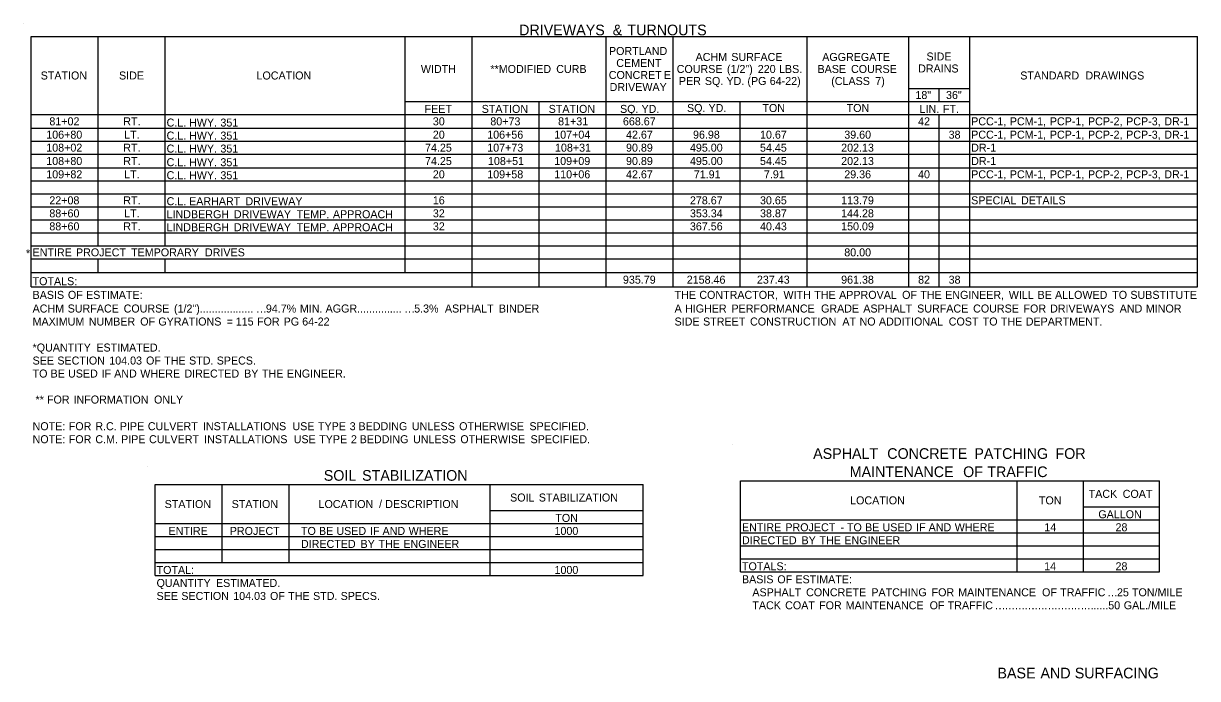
# Model space of a CAD drawing. Extents: x 1197542 to 1207068, y 230488 to 237324.
# Drawn here: x 1201721 to 1202601, y 232270 to 232761 of the extents above; entities that cross this region are included whole.
import ezdxf

# ---------------------------------------------------------------- set-up
doc = ezdxf.new("R2010")
doc.units = 0
doc.layers.add('Default', color=7, linetype='Continuous')

msp = doc.modelspace()

# ---------------------------------------------------------------- linework, layer by layer
at = {"layer": 'Default'}
for p, q in [((1201721.23, 232761.28), (1201721.23, 232761.28)), ((1201727.08, 232751.53), (1202601.17, 232751.53)), ((1201727.08, 232563.84), (1201727.08, 232751.53)), ((1201727.08, 232563.84), (1201727.08, 232751.53)), ((1201777.29, 232594.56), (1201777.29, 232751.53)), ((1201827.5, 232594.56), (1201827.5, 232751.53)), ((1202007.39, 232574.57), (1202007.39, 232751.53)), ((1202057.6, 232563.84), (1202057.6, 232751.53)), ((1202158.03, 232563.84), (1202158.03, 232751.53)), ((1202208.24, 232563.84), (1202208.24, 232751.53)), ((1202308.67, 232563.84), (1202308.67, 232751.53)), ((1202384.72, 232563.84), (1202384.72, 232751.53)), ((1202430.54, 232574.57), (1202430.54, 232751.53)), ((1202430.54, 232563.84), (1202430.54, 232751.53)), ((1202601.17, 232563.84), (1202601.17, 232751.53)), ((1202601.17, 232563.84), (1202601.17, 232751.53)), ((1202384.72, 232712.53), (1202430.54, 232712.53)), ((1202407.63, 232702.78), (1202407.63, 232712.53)), ((1202407.63, 232702.78), (1202407.63, 232712.53)), ((1202007.39, 232702.78), (1202430.54, 232702.78)), ((1202057.6, 232693.03), (1202057.6, 232702.78)), ((1202107.82, 232563.84), (1202107.82, 232702.78)), ((1202208.24, 232693.03), (1202208.24, 232702.78)), ((1202258.45, 232563.84), (1202258.45, 232702.78)), ((1202308.67, 232563.84), (1202308.67, 232702.78)), ((1202384.72, 232702.78), (1202430.54, 232702.78)), ((1201727.08, 232693.03), (1202601.17, 232693.03)), ((1201777.29, 232594.56), (1201777.29, 232693.03)), ((1201827.5, 232594.56), (1201827.5, 232693.03)), ((1202007.39, 232594.56), (1202007.39, 232693.03)), ((1202107.82, 232563.84), (1202107.82, 232693.03)), ((1202158.03, 232563.84), (1202158.03, 232693.03)), ((1202407.63, 232574.57), (1202407.63, 232693.03)), ((1202407.63, 232563.84), (1202407.63, 232693.03)), ((1202430.54, 232693.03), (1202601.17, 232693.03)), ((1201727.08, 232682.79), (1202430.54, 232682.79)), ((1202430.54, 232682.79), (1202601.17, 232682.79)), ((1202430.54, 232682.79), (1202601.17, 232682.79)), ((1201727.08, 232673.04), (1202601.17, 232673.04)), ((1202430.54, 232673.04), (1202601.17, 232673.04)), ((1201727.08, 232663.29), (1202601.17, 232663.29)), ((1201727.08, 232653.06), (1202430.54, 232653.06)), ((1202430.54, 232653.06), (1202601.17, 232653.06)), ((1202430.54, 232653.06), (1202601.17, 232653.06)), ((1201727.08, 232643.31), (1202601.17, 232643.31)), ((1202430.54, 232643.31), (1202601.17, 232643.31)), ((1201727.08, 232633.56), (1202601.17, 232633.56)), ((1201727.08, 232623.81), (1202601.17, 232623.81)), ((1201727.08, 232614.06), (1202601.17, 232614.06)), ((1201727.08, 232604.31), (1202601.17, 232604.31)), ((1201727.08, 232594.56), (1202601.17, 232594.56)), ((1201777.29, 232594.56), (1201827.5, 232594.56)), ((1201827.5, 232594.56), (1202601.17, 232594.56)), ((1201727.08, 232584.81), (1202601.17, 232584.81)), ((1201777.29, 232574.57), (1201777.29, 232584.81)), ((1201777.29, 232574.57), (1201777.29, 232584.81)), ((1201827.5, 232574.57), (1201827.5, 232584.81)), ((1201827.5, 232574.57), (1201827.5, 232584.81)), ((1202007.39, 232574.57), (1202007.39, 232584.81)), ((1201727.08, 232574.57), (1202601.17, 232574.57)), ((1202057.6, 232563.84), (1202057.6, 232574.57)), ((1202208.24, 232574.57), (1202258.45, 232574.57)), ((1202258.45, 232574.57), (1202384.72, 232574.57)), ((1202384.72, 232574.57), (1202430.54, 232574.57)), ((1202430.54, 232574.57), (1202601.17, 232574.57)), ((1201727.08, 232563.84), (1202601.17, 232563.84)), ((1202252.9, 232445.67), (1202252.9, 232445.67)), ((1201814.15, 232429.27), (1201814.15, 232429.27)), ((1202258.75, 232418.37), (1202572.7, 232418.37)), ((1202258.75, 232350.12), (1202258.75, 232418.37)), ((1202258.75, 232350.12), (1202258.75, 232418.37)), ((1202465.94, 232350.12), (1202465.94, 232418.37)), ((1202515.66, 232350.12), (1202515.66, 232418.37)), ((1202572.7, 232350.12), (1202572.7, 232418.37)), ((1202572.7, 232398.87), (1202572.7, 232418.37)), ((1201820, 232415.62), (1202185.63, 232415.62)), ((1201820, 232347.37), (1201820, 232415.62)), ((1201820, 232347.37), (1201820, 232415.62)), ((1201870.21, 232357.12), (1201870.21, 232415.62)), ((1201920.43, 232357.12), (1201920.43, 232415.62)), ((1202071.06, 232347.37), (1202071.06, 232415.62)), ((1202185.63, 232347.37), (1202185.63, 232415.62)), ((1202185.63, 232347.37), (1202185.63, 232415.62)), ((1202071.06, 232396.12), (1202185.63, 232396.12)), ((1202515.66, 232398.87), (1202572.7, 232398.87)), ((1202515.66, 232350.12), (1202515.66, 232398.87)), ((1201820, 232386.37), (1202185.63, 232386.37)), ((1201820, 232386.37), (1202185.63, 232386.37)), ((1201870.21, 232357.12), (1201870.21, 232386.37)), ((1201920.43, 232357.12), (1201920.43, 232386.37)), ((1202071.06, 232357.12), (1202071.06, 232386.37)), ((1202258.75, 232389.12), (1202572.7, 232389.12)), ((1202465.94, 232350.12), (1202465.94, 232389.12)), ((1202572.7, 232369.62), (1202572.7, 232389.12)), ((1201820, 232376.62), (1202185.63, 232376.62)), ((1202258.75, 232379.37), (1202572.7, 232379.37)), ((1201820, 232366.87), (1202185.63, 232366.87)), ((1202258.75, 232369.62), (1202572.7, 232369.62)), ((1201820, 232357.12), (1201870.21, 232357.12)), ((1201820, 232357.12), (1202185.63, 232357.12)), ((1202258.75, 232359.87), (1202572.7, 232359.87)), ((1202572.7, 232350.12), (1202572.7, 232359.87)), ((1202258.75, 232350.12), (1202572.7, 232350.12)), ((1201820, 232347.37), (1202185.63, 232347.37))]:
    msp.add_line(p, q, dxfattribs=at)

# ---------------------------------------------------------------- texts
for s, height, p in [('DRIVEWAYS', 8, (1202092.72, 232752.41)), (' &', 8, (1202159.87, 232752.41)), (' TURNOUTS', 8, (1202170.87, 232752.41)), ('PORTLAND', 6, (1202160.05, 232737.66)), ('CEMENT', 6, (1202165.52, 232728.66)), ('ACHM', 6, (1202224.96, 232733.16)), (' SURFACE', 6, (1202249.51, 232733.16)), ('AGGREGATE', 6, (1202319.88, 232733.16)), ('SIDE', 6, (1202398.05, 232733.53)), ('WIDTH', 6, (1202019.08, 232724.16)), ('**MODIFIED', 6, (1202071.2, 232724.16)), (' CURB', 6, (1202118.29, 232724.16)), ('COURSE', 6, (1202210.81, 232724.16)), (' (1/2")', 6, (1202246.26, 232724.16)), (' 220', 6, (1202269.36, 232724.16)), (' LBS.', 6, (1202285.25, 232724.16)), ('BASE', 6, (1202316.36, 232724.16)), (' COURSE', 6, (1202339.24, 232724.16)), ('DRAINS', 6, (1202391.76, 232724.53)), ('STATION', 6, (1201734.12, 232719.28)), ('SIDE', 6, (1201792.82, 232719.28)), ('LOCATION', 6, (1201895.89, 232719.28)), ('CONCRET', 6, (1202159.91, 232719.66)), ('E', 6, (1202201.19, 232719.66)), ('PER', 6, (1202212.48, 232715.16)), (' SQ.', 6, (1202229.68, 232715.16)), (' YD.', 6, (1202245.87, 232715.16)), (' (PG', 6, (1202261.6, 232715.16)), (' 64-22)', 6, (1202278.32, 232715.16)), ('(CLASS', 6, (1202326.62, 232715.16)), (' 7)', 6, (1202357.42, 232715.16)), ('STANDARD', 6, (1202468.3, 232719.28)), (' DRAWINGS', 6, (1202514.92, 232719.28)), ('DRIVEWAY', 6, (1202160.54, 232710.66)), ('18"', 6, (1202389.73, 232704.66)), ('36"', 6, (1202412.65, 232704.66)), ('FEET', 6, (1202021.87, 232694.23)), ('STATION', 6, (1202064.65, 232694.23)), ('STATION', 6, (1202114.86, 232694.23)), ('SQ.', 6, (1202168.34, 232694.23)), (' YD.', 6, (1202182.2, 232694.23)), ('SQ.', 6, (1202218.55, 232694.91)), (' YD.', 6, (1202232.42, 232694.91)), ('TON', 6, (1202275.05, 232694.91)), ('TON', 6, (1202338.18, 232694.91)), ('LIN.', 6, (1202392.84, 232694.23)), (' FT.', 6, (1202408.1, 232694.23)), ('81+02', 6, (1201740.64, 232684.91)), ('RT.', 6, (1201796.01, 232684.91)), ('30', 6, (1202028.04, 232684.91)), ('80+73', 6, (1202071.13, 232684.91)), ('81+31', 6, (1202121.93, 232684.91)), ('668.67', 6, (1202170.51, 232684.91)), ('42', 6, (1202391.73, 232684.91)), ('PCC-1,', 6, (1202431.52, 232684.91)), (' PCM-1,', 6, (1202458.25, 232684.91)), (' PCP-1,', 6, (1202488.24, 232684.91)), (' PCP-2,', 6, (1202516.84, 232684.91)), (' PCP-3,', 6, (1202545.44, 232684.91)), (' DR-1', 6, (1202574.04, 232684.91)), ('C.L.', 6, (1201828.48, 232683.99)), (' HWY.', 6, (1201843.12, 232683.99)), (' 351', 6, (1201866.6, 232683.99)), ('106+80', 6, (1201738.29, 232674.92)), ('LT.', 6, (1201796.71, 232674.92)), ('C.L.', 6, (1201828.48, 232674.24)), (' HWY.', 6, (1201843.12, 232674.24)), (' 351', 6, (1201866.6, 232674.24)), ('20', 6, (1202028.04, 232674.92)), ('106+56', 6, (1202068.8, 232674.92)), ('107+04', 6, (1202119.03, 232674.92)), ('42.67', 6, (1202172.84, 232674.92)), ('96.98', 6, (1202223.05, 232674.92)), ('10.67', 6, (1202273.27, 232674.92)), ('39.60', 6, (1202336.41, 232674.92)), ('38', 6, (1202414.61, 232674.92)), ('PCC-1,', 6, (1202431.52, 232674.92)), (' PCM-1,', 6, (1202458.25, 232674.92)), (' PCP-1,', 6, (1202488.24, 232674.92)), (' PCP-2,', 6, (1202516.84, 232674.92)), (' PCP-3,', 6, (1202545.44, 232674.92)), (' DR-1', 6, (1202574.04, 232674.92)), ('108+02', 6, (1201738.31, 232665.17)), ('RT.', 6, (1201796.01, 232665.17)), ('C.L.', 6, (1201828.48, 232664.49)), (' HWY.', 6, (1201843.12, 232664.49)), (' 351', 6, (1201866.6, 232664.49)), ('74.25', 6, (1202022.18, 232665.17)), ('107+73', 6, (1202068.8, 232665.17)), ('108+31', 6, (1202119.6, 232665.17)), ('90.89', 6, (1202172.84, 232665.17)), ('495.00', 6, (1202220.73, 232665.17)), ('54.45', 6, (1202273.24, 232665.17)), ('202.13', 6, (1202334.07, 232665.17)), ('DR-1', 6, (1202431.52, 232665.17)), ('108+80', 6, (1201738.29, 232655.17)), ('RT.', 6, (1201796.01, 232655.17)), ('C.L.', 6, (1201828.48, 232654.26)), (' HWY.', 6, (1201843.12, 232654.26)), (' 351', 6, (1201866.6, 232654.26)), ('74.25', 6, (1202022.18, 232655.17)), ('108+51', 6, (1202069.38, 232655.17)), ('109+09', 6, (1202119.01, 232655.17)), ('90.89', 6, (1202172.84, 232655.17)), ('495.00', 6, (1202220.73, 232655.17)), ('54.45', 6, (1202273.24, 232655.17)), ('202.13', 6, (1202334.07, 232655.17)), ('DR-1', 6, (1202431.52, 232655.17)), ('109+82', 6, (1201738.31, 232645.18)), ('LT.', 6, (1201796.71, 232645.18)), ('C.L.', 6, (1201828.48, 232644.51)), (' HWY.', 6, (1201843.12, 232644.51)), (' 351', 6, (1201866.6, 232644.51)), ('20', 6, (1202028.04, 232645.18)), ('109+58', 6, (1202068.8, 232645.18)), ('110+06', 6, (1202119.02, 232645.18)), ('42.67', 6, (1202172.84, 232645.18)), ('71.91', 6, (1202223.63, 232645.18)), ('7.91', 6, (1202276.18, 232645.18)), ('29.36', 6, (1202336.4, 232645.18)), ('40', 6, (1202391.71, 232645.18)), ('PCC-1,', 6, (1202431.52, 232645.18)), (' PCM-1,', 6, (1202458.25, 232645.18)), (' PCP-1,', 6, (1202488.24, 232645.18)), (' PCP-2,', 6, (1202516.84, 232645.18)), (' PCP-3,', 6, (1202545.44, 232645.18)), (' DR-1', 6, (1202574.04, 232645.18)), ('22+08', 6, (1201740.6, 232625.68)), ('RT.', 6, (1201796.01, 232625.68)), ('C.L.', 6, (1201828.48, 232625.01)), (' EARHART', 6, (1201843.12, 232625.01)), (' DRIVEWAY', 6, (1201885.34, 232625.01)), ('16', 6, (1202028.03, 232625.68)), ('278.67', 6, (1202220.72, 232625.68)), ('30.65', 6, (1202273.24, 232625.68)), ('113.79', 6, (1202334.06, 232625.68)), ('SPECIAL', 6, (1202431.52, 232625.68)), (' DETAILS', 6, (1202466.63, 232625.68)), ('88+60', 6, (1201740.62, 232615.93)), ('LT.', 6, (1201796.71, 232615.93)), ('LINDBERGH', 6, (1201828.48, 232615.26)), (' DRIVEWAY', 6, (1201876.72, 232615.26)), (' TEMP.', 6, (1201923.7, 232615.26)), (' APPROACH', 6, (1201950.92, 232615.26)), ('32', 6, (1202028.06, 232615.93)), ('353.34', 6, (1202220.74, 232615.93)), ('38.87', 6, (1202273.27, 232615.93)), ('144.28', 6, (1202334.06, 232615.93)), ('88+60', 6, (1201740.62, 232606.18)), ('RT.', 6, (1201796.01, 232606.18)), ('LINDBERGH', 6, (1201828.48, 232605.51)), (' DRIVEWAY', 6, (1201876.72, 232605.51)), (' TEMP.', 6, (1201923.7, 232605.51)), (' APPROACH', 6, (1201950.92, 232605.51)), ('32', 6, (1202028.06, 232606.18)), ('367.56', 6, (1202220.72, 232606.18)), ('40.43', 6, (1202273.27, 232606.18)), ('150.09', 6, (1202334.06, 232606.18)), ('*', 6, (1201723.14, 232586.01)), ('ENTIRE', 6, (1201728.05, 232586.68)), (' PROJECT', 6, (1201758.35, 232586.68)), (' TEMPORARY', 6, (1201799.64, 232586.68)), (' DRIVES', 6, (1201855.01, 232586.68)), ('80.00', 6, (1202336.41, 232586.68)), ('TOTALS:', 6, (1201728.05, 232565.04)), ('935.79', 6, (1202170.52, 232566.21)), ('2158.46', 6, (1202218.35, 232566.21)), ('237.43', 6, (1202270.93, 232566.21)), ('961.38', 6, (1202334.06, 232566.21)), ('82', 6, (1202391.72, 232566.21)), ('38', 6, (1202414.61, 232566.21)), ('BASIS', 6, (1201728.05, 232554.81)), (' OF', 6, (1201752.31, 232554.81)), (' ESTIMATE:', 6, (1201765.9, 232554.81)), ('THE', 6, (1202209.22, 232554.81)), (' CONTRACTOR,', 6, (1202225.54, 232554.81)), (' WITH', 6, (1202288.6, 232554.81)), (' THE', 6, (1202311.67, 232554.81)), (' APPROVAL', 6, (1202330.32, 232554.81)), (' OF', 6, (1202377.55, 232554.81)), (' THE', 6, (1202391.14, 232554.81)), (' ENGINEER,', 6, (1202409.79, 232554.81)), (' WILL', 6, (1202457.49, 232554.81)), (' BE', 6, (1202479.08, 232554.81)), (' ALLOWED', 6, (1202492.14, 232554.81)), (' TO', 6, (1202535.02, 232554.81)), (' SUBSTITUTE', 6, (1202548.61, 232554.81)), ('ACHM', 6, (1201728.05, 232544.57)), (' SURFACE', 6, (1201752.11, 232544.57)), (' COURSE', 6, (1201794.05, 232544.57)), (' (1/2")..................', 6, (1201831.81, 232544.57)), ('94.7%', 6, (1201902.9, 232544.57)), (' MIN.', 6, (1201926.15, 232544.57)), (' AGGR...............', 6, (1201945.44, 232544.57)), ('5.3%', 6, (1202014.04, 232544.57)), ('  ASPHALT', 6, (1202032.62, 232544.57)), (' BINDER', 6, (1202075.31, 232544.57)), ('A', 6, (1202209.22, 232544.57)), (' HIGHER', 6, (1202214.82, 232544.57)), (' PERFORMANCE', 6, (1202249.64, 232544.57)), (' GRADE', 6, (1202316.74, 232544.57)), (' ASPHALT', 6, (1202348.44, 232544.57)), (' SURFACE', 6, (1202388.8, 232544.57)), (' COURSE', 6, (1202430.75, 232544.57)), (' FOR', 6, (1202468.5, 232544.57)), (' DRIVEWAYS', 6, (1202488.41, 232544.57)), (' AND', 6, (1202540.62, 232544.57)), (' MINOR', 6, (1202560.2, 232544.57)), ('…', 6, (1201895.51, 232544.57)), ('…', 6, (1202006.64, 232544.57)), ('MAXIMUM', 6, (1201728.05, 232534.82)), (' NUMBER', 6, (1201767.94, 232534.82)), (' OF', 6, (1201806.49, 232534.82)), (' GYRATIONS', 6, (1201820.08, 232534.82)), (' =', 6, (1201871.35, 232534.82)), (' 115', 6, (1201878.1, 232534.82)), (' FOR', 6, (1201894.07, 232534.82)), (' PG', 6, (1201913.99, 232534.82)), (' 64-22', 6, (1201927.9, 232534.82)), ('SIDE', 6, (1202209.22, 232534.82)), (' STREET', 6, (1202228.34, 232534.82)), (' CONSTRUCTION', 6, (1202263.57, 232534.82)), (' AT', 6, (1202332.75, 232534.82)), (' NO', 6, (1202345.63, 232534.82)), (' ADDITIONAL', 6, (1202360.15, 232534.82)), (' COST', 6, (1202412.49, 232534.82)), (' TO', 6, (1202437.94, 232534.82)), (' THE', 6, (1202451.54, 232534.82)), (' DEPARTMENT.', 6, (1202470.19, 232534.82)), ('*QUANTITY', 6, (1201728.05, 232515.32)), (' ESTIMATED.', 6, (1201773.64, 232515.32)), ('SEE', 6, (1201728.05, 232505.57)), (' SECTION', 6, (1201744.38, 232505.57)), (' 104.03', 6, (1201783.29, 232505.57)), (' OF', 6, (1201810.87, 232505.57)), (' THE', 6, (1201824.46, 232505.57)), (' STD.', 6, (1201843.11, 232505.57)), (' SPECS.', 6, (1201863.8, 232505.57)), ('TO', 6, (1201728.05, 232495.82)), (' BE', 6, (1201739.32, 232495.82)), (' USED', 6, (1201752.39, 232495.82)), (' IF', 6, (1201777.56, 232495.82)), (' AND', 6, (1201786.96, 232495.82)), (' WHERE', 6, (1201806.54, 232495.82)), (' DIRECTED', 6, (1201839.63, 232495.82)), (' BY', 6, (1201884.36, 232495.82)), (' THE', 6, (1201897.81, 232495.82)), (' ENGINEER.', 6, (1201916.46, 232495.82)), (' **', 6, (1201728.05, 232476.32)), (' FOR', 6, (1201736.61, 232476.32)), (' INFORMATION', 6, (1201756.52, 232476.32)), (' ONLY', 6, (1201816.85, 232476.32)), ('NOTE:', 6, (1201728.05, 232456.33)), (' FOR', 6, (1201752.94, 232456.33)), (' R.C.', 6, (1201772.85, 232456.33)), (' PIPE', 6, (1201791.21, 232456.33)), (' CULVERT', 6, (1201812.2, 232456.33)), (' INSTALLATIONS', 6, (1201853.49, 232456.33)), (' USE', 6, (1201920.6, 232456.33)), (' TYPE', 6, (1201939.72, 232456.33)), (' 3', 6, (1201963.5, 232456.33)), (' BEDDING', 6, (1201970.11, 232456.33)), (' UNLESS', 6, (1202010.11, 232456.33)), (' OTHERWISE', 6, (1202045.55, 232456.33)), (' SPECIFIED.', 6, (1202098.2, 232456.33)), ('NOTE:', 6, (1201728.05, 232446.58)), (' FOR', 6, (1201752.94, 232446.58)), (' C.M.', 6, (1201772.85, 232446.58)), (' PIPE', 6, (1201792.14, 232446.58)), (' CULVERT', 6, (1201813.13, 232446.58)), (' INSTALLATIONS', 6, (1201854.42, 232446.58)), (' USE', 6, (1201921.53, 232446.58)), (' TYPE', 6, (1201940.65, 232446.58)), (' 2', 6, (1201964.43, 232446.58)), (' BEDDING', 6, (1201970.98, 232446.58)), (' UNLESS', 6, (1202010.98, 232446.58)), (' OTHERWISE', 6, (1202046.42, 232446.58)), (' SPECIFIED.', 6, (1202099.07, 232446.58)), ('ASPHALT', 8, (1202313.08, 232434.84)), (' CONCRETE', 8, (1202365.64, 232434.84)), (' PATCHING', 8, (1202430.92, 232434.84)), (' FOR', 8, (1202491.73, 232434.84)), ('MAINTENANCE', 8, (1202340.48, 232421.19)), (' OF', 8, (1202422.52, 232421.19)), (' TRAFFIC', 8, (1202440.63, 232421.19)), ('SOIL', 8, (1201946.3, 232418.44)), (' STABILIZATION', 8, (1201972.05, 232418.44)), ('TACK', 6, (1202519.59, 232405.62)), (' COAT', 6, (1202542.86, 232405.62)), ('STATION', 6, (1201827.04, 232397.99)), ('STATION', 6, (1201877.26, 232397.99)), ('LOCATION', 6, (1201942.38, 232397.99)), (' /', 6, (1201985.49, 232397.99)), (' DESCRIPTION', 6, (1201990.15, 232397.99)), ('SOIL', 6, (1202085.96, 232402.87)), (' STABILIZATION', 6, (1202105.27, 232402.87)), ('LOCATION', 6, (1202340.79, 232400.74)), ('TON', 6, (1202482.29, 232400.74)), ('TON', 6, (1202119.83, 232387.57)), ('GALLON', 6, (1202526.82, 232390.32)), ('ENTIRE', 6, (1201829.96, 232377.82)), ('PROJECT', 6, (1201875.84, 232377.82)), ('TO', 6, (1201929.2, 232377.82)), (' BE', 6, (1201940.47, 232377.82)), (' USED', 6, (1201953.53, 232377.82)), (' IF', 6, (1201978.71, 232377.82)), (' AND', 6, (1201988.1, 232377.82)), (' WHERE', 6, (1202007.68, 232377.82)), ('1000', 6, (1202119.22, 232377.82)), ('ENTIRE', 6, (1202259.73, 232380.57)), (' PROJECT', 6, (1202290.02, 232380.57)), (' -', 6, (1202331.31, 232380.57)), (' TO', 6, (1202336.17, 232380.57)), (' BE', 6, (1202349.77, 232380.57)), (' USED', 6, (1202362.83, 232380.57)), (' IF', 6, (1202388.01, 232380.57)), (' AND', 6, (1202397.4, 232380.57)), (' WHERE', 6, (1202416.98, 232380.57)), ('14', 6, (1202486.34, 232380.57)), ('28', 6, (1202539.71, 232380.57)), ('DIRECTED', 6, (1201929.2, 232368.07)), (' BY', 6, (1201971.61, 232368.07)), (' THE', 6, (1201985.06, 232368.07)), (' ENGINEER', 6, (1202003.71, 232368.07)), ('DIRECTED', 6, (1202259.73, 232370.82)), (' BY', 6, (1202302.13, 232370.82)), (' THE', 6, (1202315.58, 232370.82)), (' ENGINEER', 6, (1202334.23, 232370.82)), ('TOTALS:', 6, (1202259.73, 232351.32)), ('14', 6, (1202486.24, 232351.32)), ('28', 6, (1202539.71, 232351.32)), ('TOTAL:', 6, (1201820.98, 232348.57)), ('1000', 6, (1202119.23, 232348.57)), ('BASIS', 6, (1202259.73, 232341.57)), (' OF', 6, (1202283.99, 232341.57)), (' ESTIMATE:', 6, (1202297.57, 232341.57)), ('QUANTITY', 6, (1201820.98, 232338.82)), (' ESTIMATED.', 6, (1201863.3, 232338.82)), ('SEE', 6, (1201820.98, 232329.07)), (' SECTION', 6, (1201837.31, 232329.07)), (' 104.03', 6, (1201876.21, 232329.07)), (' OF', 6, (1201903.79, 232329.07)), (' THE', 6, (1201917.38, 232329.07)), (' STD.', 6, (1201936.03, 232329.07)), (' SPECS.', 6, (1201956.72, 232329.07)), ('ASPHALT', 6, (1202267.53, 232331.82)), (' CONCRETE', 6, (1202305.57, 232331.82)), (' PATCHING', 6, (1202354.49, 232331.82)), (' FOR', 6, (1202399.62, 232331.82)), (' MAINTENANCE', 6, (1202419.53, 232331.82)), (' OF', 6, (1202482.43, 232331.82)), (' TRAFFIC', 6, (1202496.02, 232331.82)), ('…', 6, (1202533.41, 232331.82)), ('25', 6, (1202540.81, 232331.82)), (' TON/MILE', 6, (1202549.8, 232331.82)), ('TACK', 6, (1202267.53, 232322.07)), (' COAT', 6, (1202289.87, 232322.07)), (' FOR', 6, (1202315.32, 232322.07)), (' MAINTENANCE', 6, (1202335.23, 232322.07)), (' OF', 6, (1202398.14, 232322.07)), (' TRAFFIC', 6, (1202411.72, 232322.07)), ('…', 6, (1202449.11, 232322.07)), ('…', 6, (1202456.51, 232322.07)), ('…', 6, (1202463.91, 232322.07)), ('…', 6, (1202471.31, 232322.07)), ('…', 6, (1202478.71, 232322.07)), ('…', 6, (1202486.11, 232322.07)), ('…', 6, (1202493.51, 232322.07)), ('…', 6, (1202500.91, 232322.07)), ('…', 6, (1202508.31, 232322.07)), ('…', 6, (1202515.71, 232322.07)), ('.....50', 6, (1202523.11, 232322.07)), (' GAL./MILE', 6, (1202543.66, 232322.07)), ('BASE', 8, (1202451.21, 232270.28)), (' AND', 8, (1202480.49, 232270.28)), (' SURFACING', 8, (1202506.19, 232270.28))]:
    msp.add_text(s, height=height, dxfattribs=at).set_placement(p)

doc.saveas('drawing.dxf')
